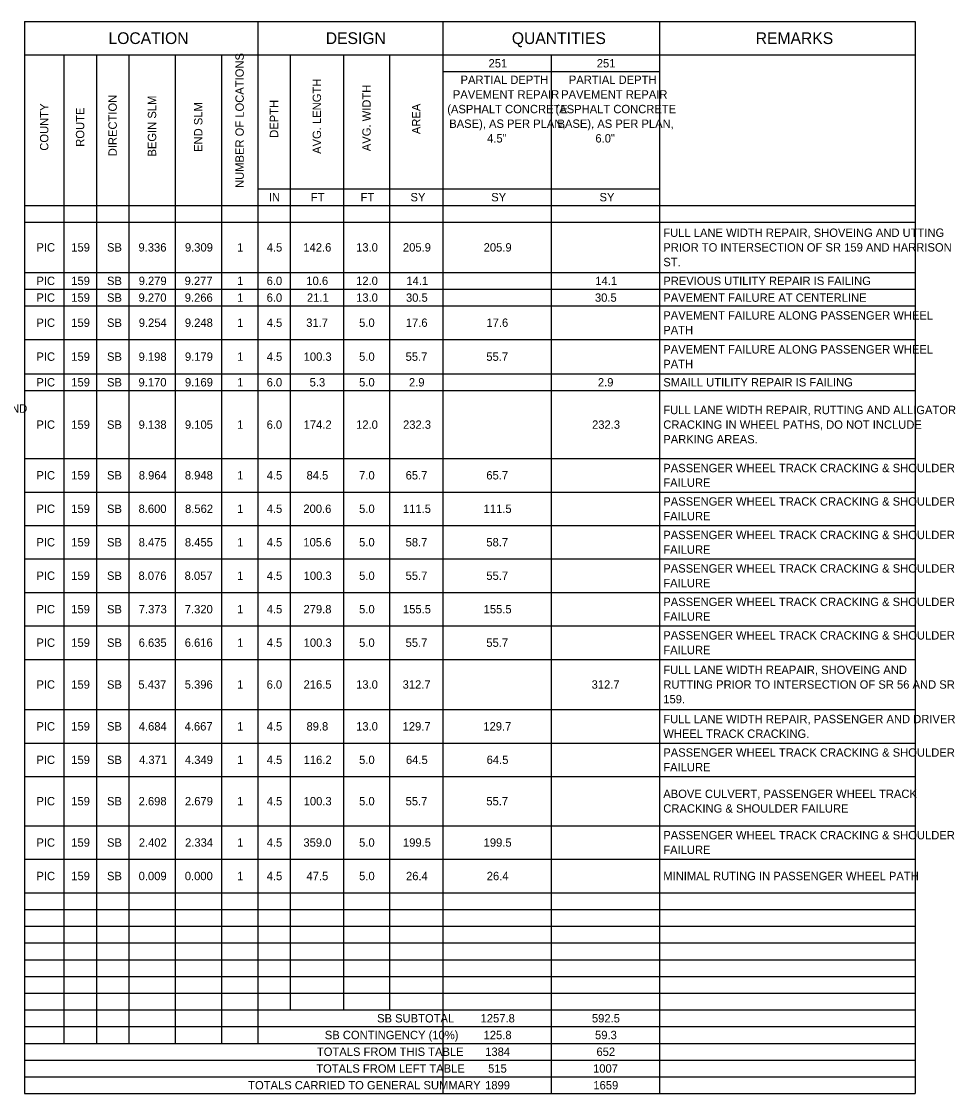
# Model space of a CAD drawing. Extents: x 0 to 66.4, y 0 to 22.
# Drawn here: x 50.75 to 66.39, y 3.83 to 21.77 of the extents above; entities that cross this region are included whole.
import ezdxf

# ---------------------------------------------------------------- set-up
doc = ezdxf.new("R2010")
doc.units = 0
doc.layers.add('Default', color=7, linetype='Continuous')
doc.layers.add('SH_Text', color=7, linetype='Continuous')

msp = doc.modelspace()

# ---------------------------------------------------------------- linework, layer by layer
at = {"layer": 'SH_Text'}
for p, q in [((50.806, 21.768), (65.712, 21.768)), ((50.806, 21.768), (50.806, 3.831)), ((54.709, 21.768), (54.709, 4.671)), ((57.806, 21.768), (57.806, 3.831)), ((61.429, 21.768), (61.429, 3.831)), ((65.712, 21.768), (65.712, 3.831)), ((50.806, 21.208), (65.712, 21.208)), ((51.465, 21.208), (51.465, 4.671)), ((52.008, 21.208), (52.008, 4.671)), ((52.552, 21.208), (52.552, 4.671)), ((53.326, 21.208), (53.326, 4.671)), ((54.1, 21.208), (54.1, 4.671)), ((55.253, 21.208), (55.253, 5.231)), ((56.142, 21.208), (56.142, 5.231)), ((56.916, 21.208), (56.916, 5.231)), ((59.618, 21.208), (59.618, 3.831)), ((57.806, 20.928), (61.429, 20.928)), ((54.709, 18.968), (61.429, 18.968)), ((50.806, 18.688), (65.712, 18.688)), ((50.806, 18.408), (65.712, 18.408)), ((50.806, 17.568), (65.712, 17.568)), ((50.806, 17.288), (65.712, 17.288)), ((50.806, 17.008), (65.712, 17.008)), ((50.806, 16.448), (65.712, 16.448)), ((50.806, 15.871), (65.712, 15.871)), ((50.806, 15.591), (65.712, 15.591)), ((50.806, 14.455), (65.712, 14.455)), ((50.806, 13.895), (65.712, 13.895)), ((50.806, 13.335), (65.712, 13.335)), ((50.806, 12.775), (65.712, 12.775)), ((50.806, 12.215), (65.712, 12.215)), ((50.806, 11.655), (65.712, 11.655)), ((50.806, 11.095), (65.712, 11.095)), ((50.806, 10.255), (65.712, 10.255)), ((50.806, 9.695), (65.712, 9.695)), ((50.806, 9.135), (65.712, 9.135)), ((50.806, 8.311), (65.712, 8.311)), ((50.806, 7.751), (65.712, 7.751)), ((50.806, 7.191), (65.712, 7.191)), ((50.806, 6.911), (65.712, 6.911)), ((50.806, 6.631), (65.712, 6.631)), ((50.806, 6.351), (65.712, 6.351)), ((50.806, 6.071), (65.712, 6.071)), ((50.806, 5.791), (65.712, 5.791)), ((50.806, 5.511), (65.712, 5.511)), ((50.806, 5.231), (65.712, 5.231)), ((50.806, 4.951), (65.712, 4.951)), ((50.806, 4.671), (65.712, 4.671)), ((50.806, 4.391), (65.712, 4.391)), ((50.806, 4.111), (65.712, 4.111)), ((50.806, 3.831), (65.712, 3.831))]:
    msp.add_line(p, q, dxfattribs=at)

# ---------------------------------------------------------------- texts
at = {"layer": 'Default'}
msp.add_text('FULL LANE WIDTH REPAIR, START REPAIR AT THE END ', height=0.14, dxfattribs=at).set_placement((45.807, 15.221))
at = {"layer": 'SH_Text'}
for s, height, p in [('LOCATION', 0.196, (52.211, 21.39)), ('DESIGN', 0.196, (55.847, 21.39)), ('QUANTITIES', 0.196, (58.961, 21.39)), ('REMARKS', 0.196, (63.042, 21.39)), ('251', 0.14, (58.571, 20.998)), ('251', 0.14, (60.382, 20.998)), ('PARTIAL DEPTH ', 0.14, (58.103, 20.722)), ('PARTIAL DEPTH ', 0.14, (59.915, 20.722)), ('PAVEMENT REPAIR ', 0.14, (57.974, 20.477)), ('PAVEMENT REPAIR ', 0.14, (59.786, 20.477)), ('(ASPHALT CONCRETE ', 0.14, (57.88, 20.232)), ('(ASPHALT CONCRETE ', 0.14, (59.692, 20.232)), ('BASE), AS PER PLAN, ', 0.14, (57.913, 19.987)), ('BASE), AS PER PLAN, ', 0.14, (59.725, 19.987)), ('4.5"', 0.14, (58.547, 19.742)), ('6.0"', 0.14, (60.359, 19.742)), ('IN', 0.14, (54.895, 18.758)), ('FT', 0.14, (55.597, 18.758)), ('FT', 0.14, (56.429, 18.758)), ('SY', 0.14, (57.265, 18.758)), ('SY', 0.14, (58.616, 18.758)), ('SY', 0.14, (60.428, 18.758)), ('FULL LANE WIDTH REPAIR, SHOVEING AND UTTING ', 0.14, (61.495, 18.163)), ('PIC', 0.14, (51.005, 17.918)), ('159', 0.14, (51.588, 17.918)), ('SB', 0.14, (52.186, 17.918)), ('9.336', 0.14, (52.713, 17.918)), ('9.309', 0.14, (53.49, 17.918)), ('1', 0.14, (54.364, 17.918)), ('4.5', 0.14, (54.859, 17.918)), ('142.6', 0.14, (55.472, 17.918)), ('13.0', 0.14, (56.355, 17.918)), ('205.9', 0.14, (57.138, 17.918)), ('205.9', 0.14, (58.489, 17.918)), ('PRIOR TO INTERSECTION OF SR 159 AND HARRISON ', 0.14, (61.495, 17.918)), ('ST.', 0.14, (61.495, 17.673)), ('PIC', 0.14, (51.005, 17.358)), ('159', 0.14, (51.588, 17.358)), ('SB', 0.14, (52.186, 17.358)), ('9.279', 0.14, (52.716, 17.358)), ('9.277', 0.14, (53.485, 17.358)), ('1', 0.14, (54.364, 17.358)), ('6.0', 0.14, (54.857, 17.358)), ('10.6', 0.14, (55.522, 17.358)), ('12.0', 0.14, (56.355, 17.358)), ('14.1', 0.14, (57.196, 17.358)), ('14.1', 0.14, (60.358, 17.358)), ('PREVIOUS UTILITY REPAIR IS FAILING', 0.14, (61.495, 17.358)), ('PIC', 0.14, (51.005, 17.078)), ('159', 0.14, (51.588, 17.078)), ('SB', 0.14, (52.186, 17.078)), ('9.270', 0.14, (52.714, 17.078)), ('9.266', 0.14, (53.487, 17.078)), ('6.0', 0.14, (54.857, 17.078)), ('21.1', 0.14, (55.532, 17.078)), ('13.0', 0.14, (56.355, 17.078)), ('30.5', 0.14, (57.189, 17.078)), ('30.5', 0.14, (60.351, 17.078)), ('PAVEMENT FAILURE AT CENTERLINE', 0.14, (61.495, 17.078)), ('1', 0.14, (54.364, 17.078)), ('PAVEMENT FAILURE ALONG PASSENGER WHEEL ', 0.14, (61.495, 16.78)), ('PIC', 0.14, (51.005, 16.658)), ('159', 0.14, (51.588, 16.658)), ('SB', 0.14, (52.186, 16.658)), ('9.254', 0.14, (52.718, 16.658)), ('9.248', 0.14, (53.489, 16.658)), ('1', 0.14, (54.364, 16.658)), ('4.5', 0.14, (54.859, 16.658)), ('31.7', 0.14, (55.52, 16.658)), ('5.0', 0.14, (56.405, 16.658)), ('17.6', 0.14, (57.186, 16.658)), ('17.6', 0.14, (58.536, 16.658)), ('PATH', 0.14, (61.495, 16.535)), ('PAVEMENT FAILURE ALONG PASSENGER WHEEL ', 0.14, (61.495, 16.212)), ('PIC', 0.14, (51.005, 16.09)), ('159', 0.14, (51.588, 16.09)), ('SB', 0.14, (52.186, 16.09)), ('9.198', 0.14, (52.715, 16.09)), ('9.179', 0.14, (53.49, 16.09)), ('1', 0.14, (54.364, 16.09)), ('4.5', 0.14, (54.859, 16.09)), ('100.3', 0.14, (55.477, 16.09)), ('5.0', 0.14, (56.405, 16.09)), ('55.7', 0.14, (57.183, 16.09)), ('55.7', 0.14, (58.534, 16.09)), ('PATH', 0.14, (61.495, 15.967)), ('PIC', 0.14, (51.005, 15.661)), ('159', 0.14, (51.588, 15.661)), ('SB', 0.14, (52.186, 15.661)), ('9.170', 0.14, (52.714, 15.661)), ('9.169', 0.14, (53.49, 15.661)), ('1', 0.14, (54.364, 15.661)), ('6.0', 0.14, (54.857, 15.661)), ('5.3', 0.14, (55.577, 15.661)), ('5.0', 0.14, (56.405, 15.661)), ('2.9', 0.14, (57.239, 15.661)), ('2.9', 0.14, (60.401, 15.661)), ('SMAILL UTILITY REPAIR IS FAILING', 0.14, (61.495, 15.661)), ('FULL LANE WIDTH REPAIR, RUTTING AND ALLIGATOR ', 0.14, (61.495, 15.198)), ('PIC', 0.14, (51.005, 14.953)), ('159', 0.14, (51.588, 14.953)), ('SB', 0.14, (52.186, 14.953)), ('9.138', 0.14, (52.715, 14.953)), ('9.105', 0.14, (53.49, 14.953)), ('1', 0.14, (54.364, 14.953)), ('6.0', 0.14, (54.857, 14.953)), ('174.2', 0.14, (55.477, 14.953)), ('12.0', 0.14, (56.355, 14.953)), ('232.3', 0.14, (57.14, 14.953)), ('232.3', 0.14, (60.303, 14.953)), ('CRACKING IN WHEEL PATHS, DO NOT INCLUDE ', 0.14, (61.495, 14.953)), ('PARKING AREAS.', 0.14, (61.495, 14.708)), ('PASSENGER WHEEL TRACK CRACKING & SHOULDER ', 0.14, (61.495, 14.227)), ('PIC', 0.14, (51.005, 14.105)), ('159', 0.14, (51.588, 14.105)), ('SB', 0.14, (52.186, 14.105)), ('8.964', 0.14, (52.718, 14.105)), ('8.948', 0.14, (53.489, 14.105)), ('1', 0.14, (54.364, 14.105)), ('4.5', 0.14, (54.859, 14.105)), ('84.5', 0.14, (55.525, 14.105)), ('7.0', 0.14, (56.405, 14.105)), ('65.7', 0.14, (57.183, 14.105)), ('65.7', 0.14, (58.534, 14.105)), ('FAILURE', 0.14, (61.495, 13.982)), ('PIC', 0.14, (51.005, 13.545)), ('159', 0.14, (51.588, 13.545)), ('SB', 0.14, (52.186, 13.545)), ('8.600', 0.14, (52.714, 13.545)), ('8.562', 0.14, (53.492, 13.545)), ('1', 0.14, (54.364, 13.545)), ('4.5', 0.14, (54.859, 13.545)), ('200.6', 0.14, (55.472, 13.545)), ('5.0', 0.14, (56.405, 13.545)), ('111.5', 0.14, (57.139, 13.545)), ('111.5', 0.14, (58.489, 13.545)), ('PASSENGER WHEEL TRACK CRACKING & SHOULDER ', 0.14, (61.495, 13.667)), ('FAILURE', 0.14, (61.495, 13.422)), ('PIC', 0.14, (51.005, 12.985)), ('159', 0.14, (51.588, 12.985)), ('SB', 0.14, (52.186, 12.985)), ('8.475', 0.14, (52.716, 12.985)), ('8.455', 0.14, (53.49, 12.985)), ('1', 0.14, (54.364, 12.985)), ('4.5', 0.14, (54.859, 12.985)), ('105.6', 0.14, (55.472, 12.985)), ('5.0', 0.14, (56.405, 12.985)), ('58.7', 0.14, (57.183, 12.985)), ('58.7', 0.14, (58.534, 12.985)), ('PASSENGER WHEEL TRACK CRACKING & SHOULDER ', 0.14, (61.495, 13.107)), ('FAILURE', 0.14, (61.495, 12.862)), ('PIC', 0.14, (51.005, 12.425)), ('159', 0.14, (51.588, 12.425)), ('SB', 0.14, (52.186, 12.425)), ('8.076', 0.14, (52.713, 12.425)), ('8.057', 0.14, (53.485, 12.425)), ('1', 0.14, (54.364, 12.425)), ('4.5', 0.14, (54.859, 12.425)), ('100.3', 0.14, (55.477, 12.425)), ('5.0', 0.14, (56.405, 12.425)), ('55.7', 0.14, (57.183, 12.425)), ('55.7', 0.14, (58.534, 12.425)), ('PASSENGER WHEEL TRACK CRACKING & SHOULDER ', 0.14, (61.495, 12.547)), ('FAILURE', 0.14, (61.495, 12.302)), ('PASSENGER WHEEL TRACK CRACKING & SHOULDER ', 0.14, (61.495, 11.987)), ('PIC', 0.14, (51.005, 11.865)), ('159', 0.14, (51.588, 11.865)), ('SB', 0.14, (52.186, 11.865)), ('7.373', 0.14, (52.718, 11.865)), ('7.320', 0.14, (53.488, 11.865)), ('1', 0.14, (54.364, 11.865)), ('4.5', 0.14, (54.859, 11.865)), ('279.8', 0.14, (55.474, 11.865)), ('5.0', 0.14, (56.405, 11.865)), ('155.5', 0.14, (57.139, 11.865)), ('155.5', 0.14, (58.489, 11.865)), ('FAILURE', 0.14, (61.495, 11.742)), ('PASSENGER WHEEL TRACK CRACKING & SHOULDER ', 0.14, (61.495, 11.427)), ('PIC', 0.14, (51.005, 11.305)), ('159', 0.14, (51.588, 11.305)), ('SB', 0.14, (52.186, 11.305)), ('6.635', 0.14, (52.716, 11.305)), ('6.616', 0.14, (53.487, 11.305)), ('1', 0.14, (54.364, 11.305)), ('4.5', 0.14, (54.859, 11.305)), ('100.3', 0.14, (55.477, 11.305)), ('5.0', 0.14, (56.405, 11.305)), ('55.7', 0.14, (57.183, 11.305)), ('55.7', 0.14, (58.534, 11.305)), ('FAILURE', 0.14, (61.495, 11.182)), ('FULL LANE WIDTH REAPAIR, SHOVEING AND ', 0.14, (61.495, 10.85)), ('PIC', 0.14, (51.005, 10.605)), ('159', 0.14, (51.588, 10.605)), ('SB', 0.14, (52.186, 10.605)), ('5.437', 0.14, (52.711, 10.605)), ('5.396', 0.14, (53.487, 10.605)), ('1', 0.14, (54.364, 10.605)), ('6.0', 0.14, (54.857, 10.605)), ('216.5', 0.14, (55.475, 10.605)), ('13.0', 0.14, (56.355, 10.605)), ('312.7', 0.14, (57.133, 10.605)), ('312.7', 0.14, (60.295, 10.605)), ('RUTTING PRIOR TO INTERSECTION OF SR 56 AND SR ', 0.14, (61.495, 10.605)), ('159.', 0.14, (61.495, 10.36)), ('PIC', 0.14, (51.005, 9.905)), ('159', 0.14, (51.588, 9.905)), ('SB', 0.14, (52.186, 9.905)), ('4.684', 0.14, (52.718, 9.905)), ('4.667', 0.14, (53.485, 9.905)), ('1', 0.14, (54.364, 9.905)), ('4.5', 0.14, (54.859, 9.905)), ('89.8', 0.14, (55.524, 9.905)), ('13.0', 0.14, (56.355, 9.905)), ('129.7', 0.14, (57.133, 9.905)), ('129.7', 0.14, (58.484, 9.905)), ('FULL LANE WIDTH REPAIR, PASSENGER AND DRIVER ', 0.14, (61.495, 10.027)), ('WHEEL TRACK CRACKING.', 0.14, (61.495, 9.782)), ('PASSENGER WHEEL TRACK CRACKING & SHOULDER ', 0.14, (61.495, 9.467)), ('PIC', 0.14, (51.005, 9.345)), ('159', 0.14, (51.588, 9.345)), ('SB', 0.14, (52.186, 9.345)), ('4.371', 0.14, (52.723, 9.345)), ('4.349', 0.14, (53.49, 9.345)), ('1', 0.14, (54.364, 9.345)), ('4.5', 0.14, (54.859, 9.345)), ('116.2', 0.14, (55.477, 9.345)), ('5.0', 0.14, (56.405, 9.345)), ('64.5', 0.14, (57.189, 9.345)), ('64.5', 0.14, (58.539, 9.345)), ('FAILURE', 0.14, (61.495, 9.222)), ('PIC', 0.14, (51.005, 8.653)), ('159', 0.14, (51.588, 8.653)), ('SB', 0.14, (52.186, 8.653)), ('2.698', 0.14, (52.715, 8.653)), ('2.679', 0.14, (53.49, 8.653)), ('1', 0.14, (54.364, 8.653)), ('4.5', 0.14, (54.859, 8.653)), ('100.3', 0.14, (55.477, 8.653)), ('5.0', 0.14, (56.405, 8.653)), ('55.7', 0.14, (57.183, 8.653)), ('55.7', 0.14, (58.534, 8.653)), ('ABOVE CULVERT, PASSENGER WHEEL TRACK ', 0.14, (61.495, 8.776)), ('CRACKING & SHOULDER FAILURE', 0.14, (61.495, 8.531)), ('PIC', 0.14, (51.005, 7.961)), ('159', 0.14, (51.588, 7.961)), ('SB', 0.14, (52.186, 7.961)), ('2.402', 0.14, (52.718, 7.961)), ('2.334', 0.14, (53.492, 7.961)), ('1', 0.14, (54.364, 7.961)), ('4.5', 0.14, (54.859, 7.961)), ('359.0', 0.14, (55.473, 7.961)), ('5.0', 0.14, (56.405, 7.961)), ('199.5', 0.14, (57.139, 7.961)), ('199.5', 0.14, (58.489, 7.961)), ('PASSENGER WHEEL TRACK CRACKING & SHOULDER ', 0.14, (61.495, 8.084)), ('FAILURE', 0.14, (61.495, 7.839)), ('PIC', 0.14, (51.005, 7.401)), ('159', 0.14, (51.588, 7.401)), ('SB', 0.14, (52.186, 7.401)), ('0.009', 0.14, (52.716, 7.401)), ('0.000', 0.14, (53.488, 7.401)), ('1', 0.14, (54.364, 7.401)), ('4.5', 0.14, (54.859, 7.401)), ('47.5', 0.14, (55.525, 7.401)), ('5.0', 0.14, (56.405, 7.401)), ('26.4', 0.14, (57.19, 7.401)), ('26.4', 0.14, (58.541, 7.401)), ('MINIMAL RUTING IN PASSENGER WHEEL PATH', 0.14, (61.495, 7.401)), ('SB SUBTOTAL', 0.14, (56.706, 5.021)), ('1257.8', 0.14, (58.438, 5.021)), ('592.5', 0.14, (60.301, 5.021)), ('SB CONTINGENCY (10%)', 0.14, (55.831, 4.741)), ('125.8', 0.14, (58.488, 4.741)), ('59.3', 0.14, (60.353, 4.741)), ('TOTALS FROM THIS TABLE', 0.14, (55.699, 4.461)), ('1384', 0.14, (58.515, 4.461)), ('652', 0.14, (60.377, 4.461)), ('TOTALS FROM LEFT TABLE', 0.14, (55.688, 4.181)), ('515', 0.14, (58.564, 4.181)), ('1007', 0.14, (60.32, 4.181)), ('TOTALS CARRIED TO GENERAL SUMMARY', 0.14, (54.549, 3.901)), ('1899', 0.14, (58.513, 3.901)), ('1659', 0.14, (60.325, 3.901))]:
    msp.add_text(s, height=height, dxfattribs=at).set_placement(p)
for s, p in [('NUMBER OF LOCATIONS', (54.475, 18.982)), ('AVG. LENGTH', (55.768, 19.552)), ('AVG. WIDTH', (56.599, 19.597)), ('DIRECTION', (52.35, 19.512)), ('BEGIN SLM', (53.009, 19.507)), ('COUNTY', (51.205, 19.605)), ('ROUTE', (51.806, 19.671)), ('END SLM', (53.783, 19.585)), ('DEPTH', (55.051, 19.821)), ('AREA', (57.431, 19.882))]:
    msp.add_text(s, height=0.14, rotation=90, dxfattribs=at).set_placement(p)

doc.saveas('drawing.dxf')
